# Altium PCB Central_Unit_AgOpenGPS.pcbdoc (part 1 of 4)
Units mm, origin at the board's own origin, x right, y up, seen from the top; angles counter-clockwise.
Board outline 200.19 x 122.57 mm, 2 copper layers (Top Layer, Bottom Layer); 271 components, 213 nets, 1023 pads, 412 vias.
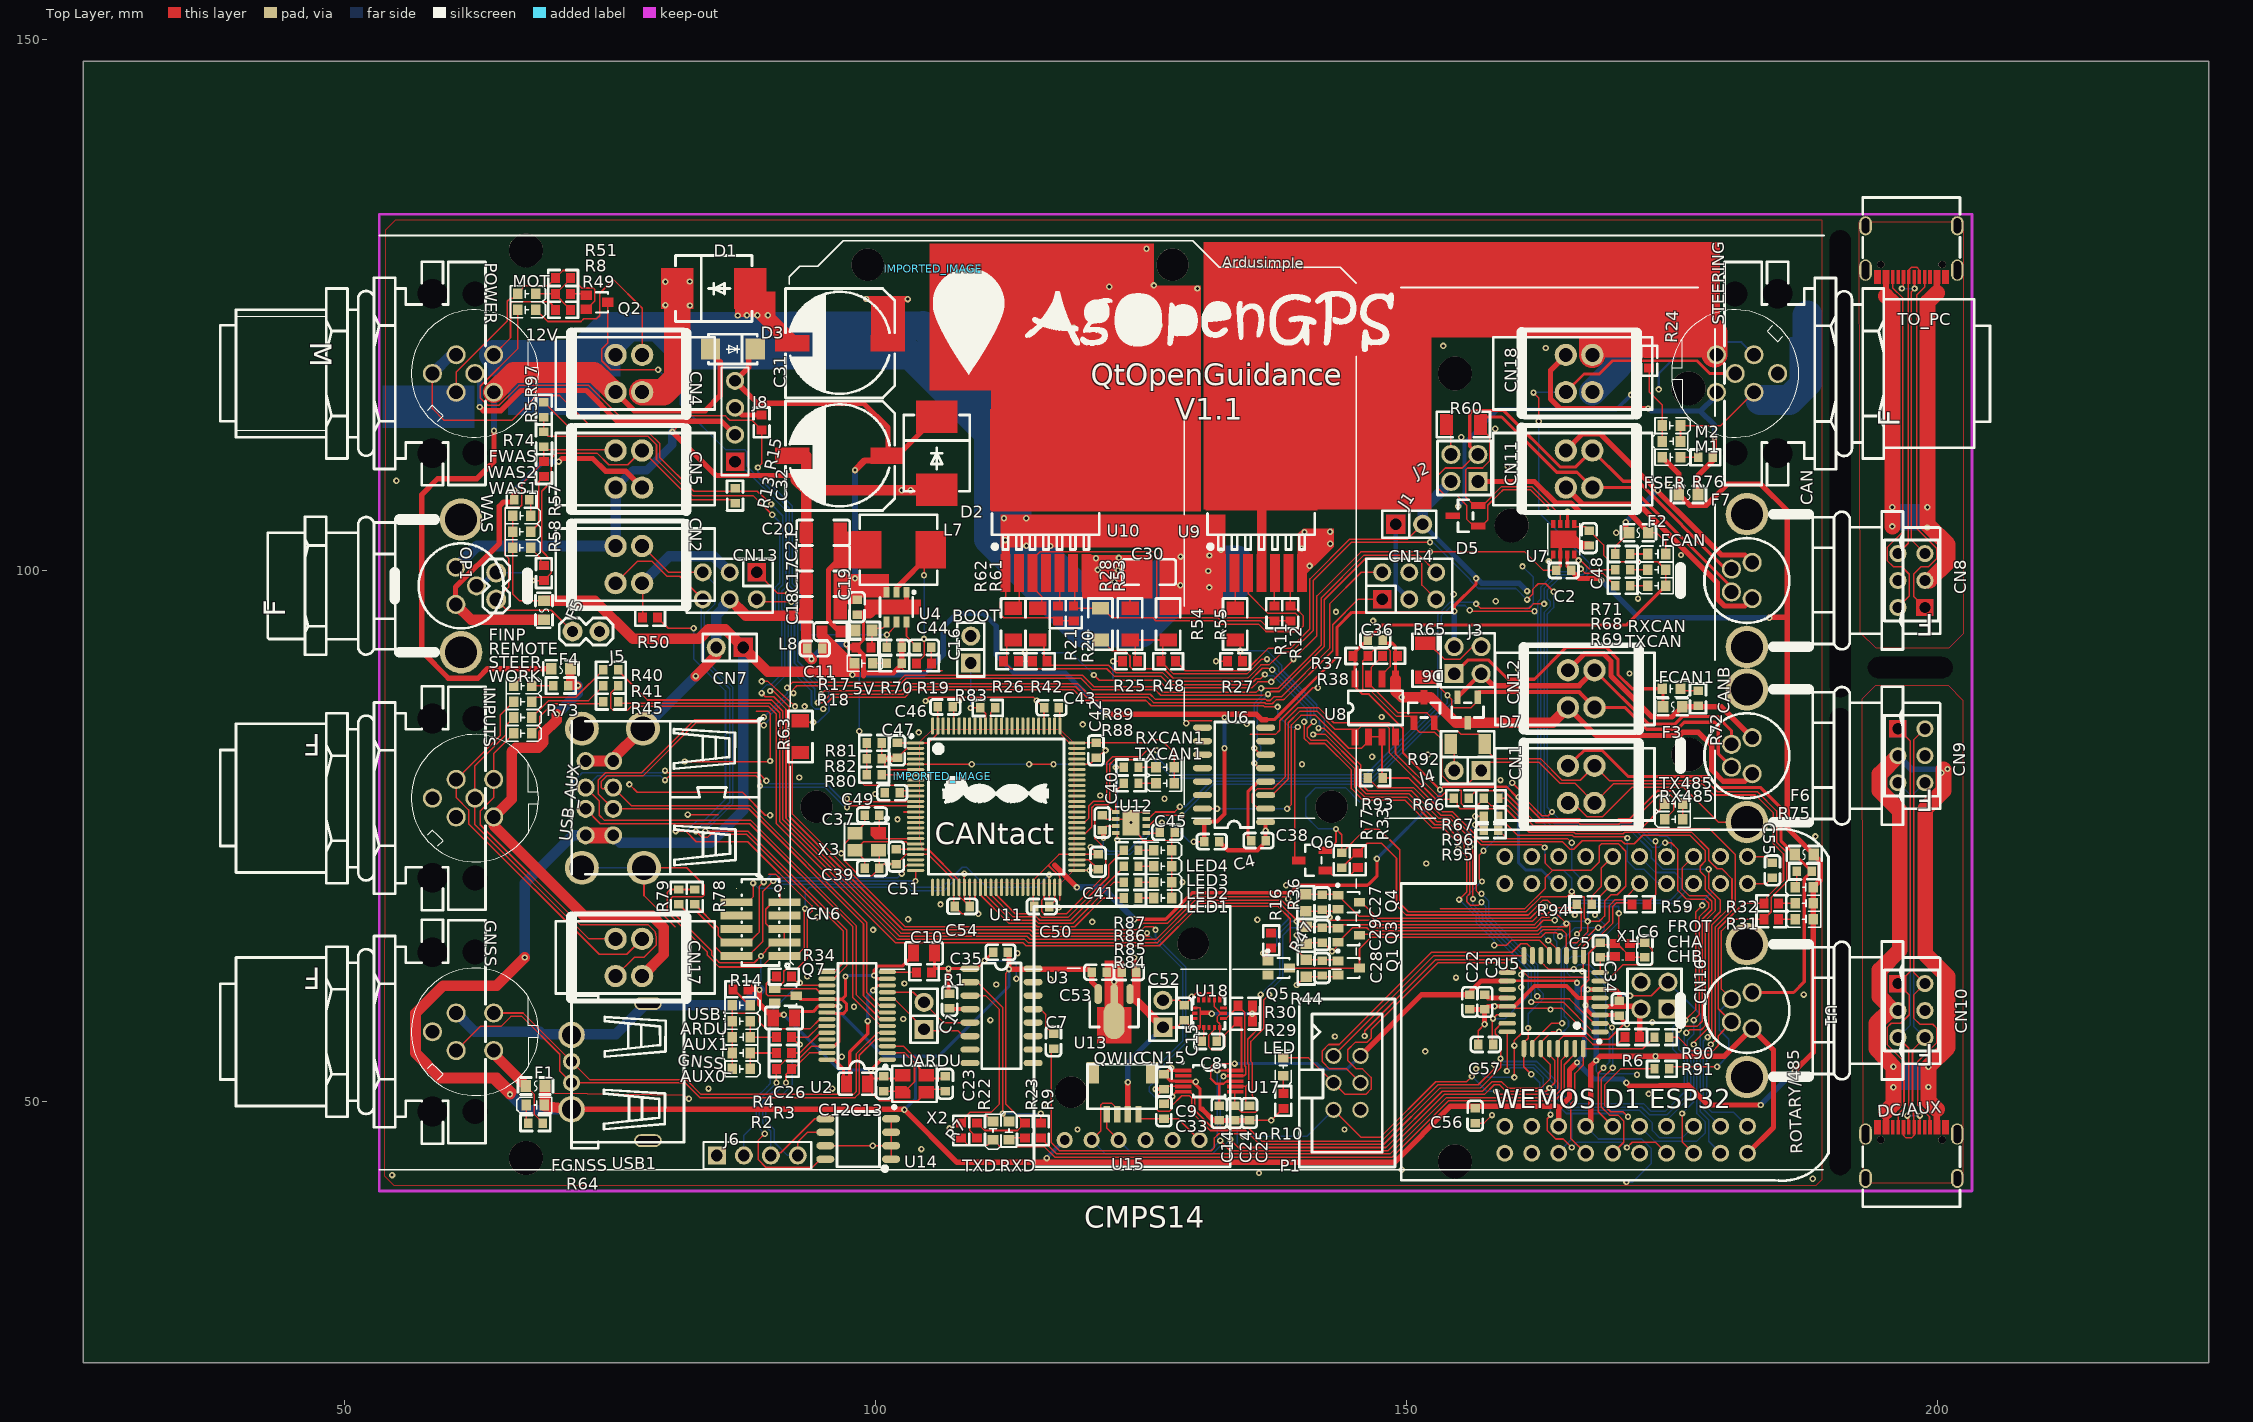
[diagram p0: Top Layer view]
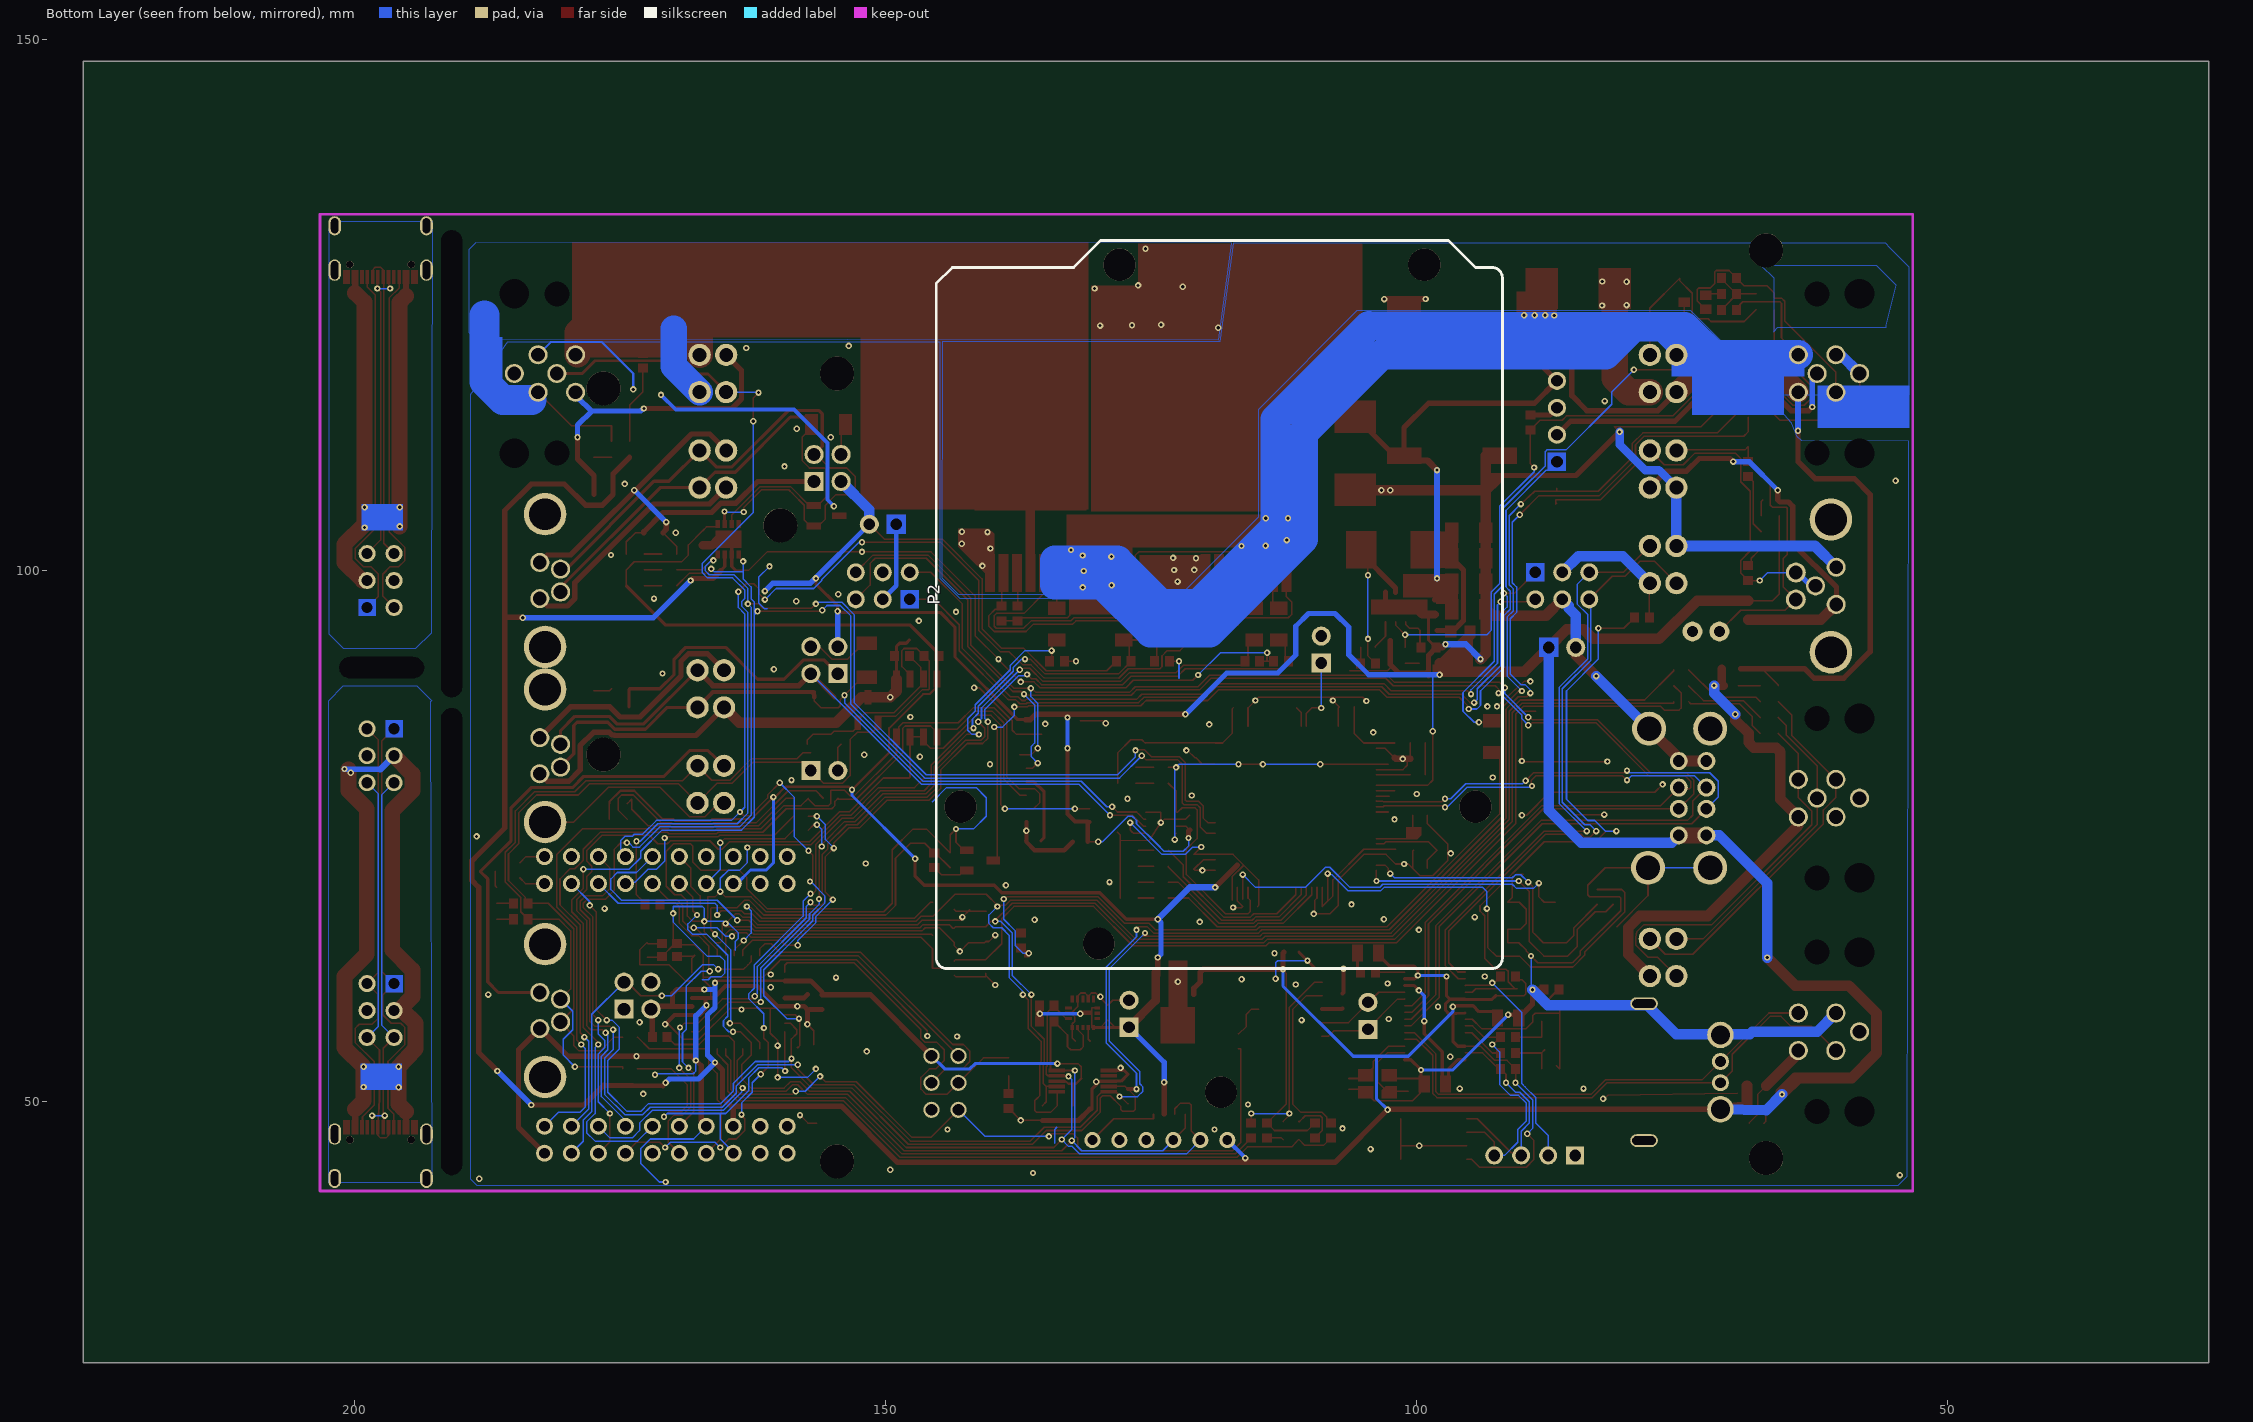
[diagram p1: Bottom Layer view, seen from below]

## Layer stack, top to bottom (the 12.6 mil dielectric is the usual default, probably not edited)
Top Layer: signal copper (thickness not stored)
Dielectric: dielectric 0.32, FR-4, Dk 4.8
Bottom Layer: signal copper (thickness not stored)

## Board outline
225.587,25.4 25.4,25.4 25.4,147.973 225.587,147.973

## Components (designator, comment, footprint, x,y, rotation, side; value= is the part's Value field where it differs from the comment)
5V "FC-D1608WD-460H5" LED0603-RD 98.887,91.266 r180 top
12V "FC-D1608WD-460H5" LED0603-RD 67.187,124.566 r180 top
ARDU "FC-D1608UGK-520D10" LED0603-RD 87.387,57.566 r180 top
AUX0 "FC-D1608UGK-520D10" LED0603-RD 87.387,53.066 r180 top
AUX1 "FC-DA1608BK-470H10" LED0603-RD 87.387,56.066 r0 top
BOOT "A2541WV-2P" HDR-TH_P2.54-H-M_A2541WV-2P#1 108.987,92.566 r90 top
C1 "1uF" C0603 106.987,59.466 r270 top
C2 "1uF" C0603 164.837,100.016 r180 top
C3 "100nF" C0603 157.387,59.366 r270 top
C4 "100nF" C0603 131.687,74.466 r0 top
C5 "22pF" C0603 168.287,64.266 r270 top
C6 "22pF" C0603 172.487,64.266 r90 top
C7 "100nF" C0603 116.787,55.666 r90 top
C8 "100nF" C0603 131.437,55.666 r180 top
C9 "100nF" C0603 127.187,51.866 r270 top
C10 "10uF" C0805 104.587,63.966 r180 top
C11 "1uF" C0603 94.287,92.666 r180 top
C12 "10uF" C0805 98.287,51.666 r180 top
C13 "33pF" C0603 100.787,51.666 r270 top
C14 "1uF" C0603 132.387,48.916 r270 top
C15 "1uF" C0603 129.087,58.366 r90 top
C16 "100nF" C0603 104.587,92.766 r0 top
C17 "10uF" C1206 95.087,98.766 r0 top
C18 "10uF" C1206 95.087,96.366 r0 top
C19 "100nF" C0603 98.287,96.566 r90 top
C20 "22uF" C1206 95.087,103.566 r0 top
C21 "22uF" C1206 95.087,101.166 r0 top
C22 "1uF" C0603 155.987,59.366 r270 top
C23 "33pF" C0603 106.587,51.666 r270 top
C24 "1nF" C0603 133.839,48.917 r90 top
C25 "1nF" C0603 135.239,48.917 r90 top
C26 "10uF" C0805 91.387,57.866 r180 top
C27 "100nF" C0603 142.087,68.766 r90 top
C28 "100nF" C0603 142.087,62.566 r90 top
C29 "100nF" C0603 142.087,65.666 r90 top
C30 "10uF" C1206 125.787,99.866 r180 top
C31 "470uF" CAP-SMD_BD10.0-L10.3-W10.3-FD 96.687,121.416 r180 top
C32 "470uF" CAP-SMD_BD10.0-L10.3-W10.3-FD 96.687,110.816 r180 top
C33 "100nF" C0603 127.187,49.066 r90 top
C34 "1uF" C0603 170.087,58.766 r270 top
C35 "1uF" C0603 111.787,64.066 r180 top
C36 "1uF" C0603 147.087,93.466 r0 top
C37 "33pF" C0603 99.687,76.966 r0 top
C38 "100nF" C0603 136.087,74.566 r0 top
C39 "33pF" C0603 99.687,71.966 r180 top
C40 "1uF" C0603 121.387,76.266 r90 top
C41 "1uF" C0603 120.987,72.566 r90 top
C42 "1uF" C0603 120.787,83.066 r90 top
C43 "1uF" C0603 116.587,87.066 r0 top
C44 "100nF" C0603 101.787,92.766 r180 top
C45 "100nF" C0603 127.487,75.366 r180 top
C46 "1uF" C0603 106.587,87.166 r180 top
C47 "1uF" C0603 102.087,83.066 r90 top
C48 "100nF" C0603 167.237,103.066 r90 top
C49 "1uF" C0603 101.587,79.066 r0 top
C50 "1uF" C0603 115.687,68.366 r180 top
C51 "1uF" C0603 101.987,73.066 r90 top
C52 "1uF" C0603 123.887,62.166 r180 top
C53 "1uF" C0603 121.087,62.166 r0 top
C54 "1uF" C0603 108.187,68.366 r0 top
C55 "100nF" C0603 184.487,71.766 r270 top
C56 "1uF" C0603 156.487,48.666 r270 top
C57 "1nF" C0603 157.487,55.366 r0 top
CAN "M8 4pole female" "M8 FEMALE 4POLE 90°" 182.087,99.066 r90 top
CANB "M8 4pole female" "M8 FEMALE 4POLE 90°" 182.087,82.566 r90 top
CHA "FC-D1608HYK-588J" LED0603-RD 187.487,68.666 r0 top
CHB "FC-D1608HOK-600H" LED0603-RD 187.487,67.166 r0 top
CN1 "4x1 push_in connector" "S2C-SMT 3.50/04/180G 3.5SN BK RL" 166.487,79.866 r270 top
CN2 "4x1 push_in connector" "S2C-SMT 3.50/04/180G 3.5SN BK RL" 76.787,100.566 r90 top
CN4 "4x1 push_in connector" "S2C-SMT 3.50/04/180G 3.5SN BK RL" 76.787,118.566 r90 top
CN5 "4x1 push_in connector" "S2C-SMT 3.50/04/180G 3.5SN BK RL" 76.787,109.566 r90 top
CN6 "1315-1206G0M075CP01" HDR-SMD_12P-P1.27-V-M-R2-C6-S7.50 89.187,66.866 r90 top
CN7 "A2541WV-2P" HDR-TH_P2.54-H-M_A2541WV-2P#2 86.287,92.766 r180 top
CN8 "A2541WV-2X3P" HDR-TH_6P-P2.54-V-R2-C3-S2.54_A2541WV-2X3P 197.587,99.066 r90 top
CN9 "A2541WV-2X3P" HDR-TH_6P-P2.54-V-R2-C3-S2.54_A2541WV-2X3P 197.587,82.566 r270 top
CN10 "A2541WV-2X3P" HDR-TH_6P-P2.54-V-R2-C3-S2.54_A2541WV-2X3P 197.587,58.566 r270 top
CN11 "4x1 push_in connector" "S2C-SMT 3.50/04/180G 3.5SN BK RL" 166.287,109.566 r270 top
CN12 "4x1 push_in connector" "S2C-SMT 3.50/04/180G 3.5SN BK RL" 166.487,88.866 r270 top
CN13 "PM254V-12-06-H85" HDR-TH_6P-P2.54-V-F-R2-C3-S2.54 86.287,98.566 r180 top
CN14 "PM254V-12-06-H85" HDR-TH_6P-P2.54-V-F-R2-C3-S2.54 150.287,98.566 r0 top
CN15 "A2541WV-2P" HDR-TH_P2.54-H-M_A2541WV-2P#1 127.087,58.266 r90 top
CN16 "A2541WV-2X2P" HDR-TH_4P-P2.54-V-R2-C2-S2.54_A2541WV-2X2P 173.387,59.966 r90 top
CN17 "4x1 push_in connector" "S2C-SMT 3.50/04/180G 3.5SN BK RL" 76.787,63.566 r90 top
CN18 "4x1 push_in connector" "S2C-SMT 3.50/04/180G 3.5SN BK RL" 166.287,118.566 r270 top
D1 "SMCJ28A-C140808" SMC_L6.9-W5.9-LS7.9-RD 84.787,126.566 r0 top
D2 "SMCJ28A-C140808" SMC_L6.9-W5.9-LS7.9-RD 105.787,111.066 r270 top
D3 "SS34_C83961" SMA_L4.4-W2.8-LS5.4-RD 86.587,120.866 r180 top
D5 "CDSOT23-T24CAN" SOT-23_L2.9-W1.3-P0.95-LS2.4-BR#1 155.587,105.166 r0 top
D6 "CDSOT23-T24CAN" SOT-23_L2.9-W1.3-P0.95-LS2.4-BR#1 151.687,86.866 r270 top
D7 "CDSOT23-T24CAN" SOT-23_L2.9-W1.3-P0.95-LS2.4-BR#2 155.787,86.866 r90 top
DC/AUX "KH-TYPE-C-16P" USB-C-SMD_KH-TYPE-C-16P#1 197.587,45.166 r0 top
F1 "BSMD0603-050-6V" F0603 67.987,51.466 r0 top
F2 "BSMD0603-050-6V" F0603 171.887,103.566 r180 top
F3 "BSMD0603-050-6V" F0603 175.087,87.166 r0 top
F4 "BSMD0603-050-6V" F0603 70.387,90.766 r0 top
F5 "BSMD0603-050-6V" F0603 68.787,96.266 r270 top
F6 "BSMD0603-050-6V" F0603 187.487,73.266 r180 top
F7 "BSMD0603-050-6V" F0603 176.587,107.166 r0 top
FCAN "FC-DA1608HRK-620D" LED0603-FD 173.587,101.566 r180 top
FCAN1 "FC-DA1608HRK-620D" LED0603-FD 174.988,88.867 r0 top
FGNSS "FC-DA1608HRK-620D" LED0603-FD 67.987,49.666 r180 top
FINP "FC-DA1608HRK-620D" LED0603-FD 66.787,89.166 r0 top
FROT "FC-DA1608HRK-620D" LED0603-FD 187.487,70.166 r180 top
FSER "FC-DA1608HRK-620D" LED0603-FD 174.987,110.666 r0 top
FWAS "FC-DA1608HRK-620D" LED0603-FD 66.687,105.166 r0 top
GNSS "M12 4pole female" "M12-D FEMALE 4POLE 90°" 62.287,56.566 r90 top
GNSS_ "FC-DA1608BK-470H10" LED0603-RD 87.387,54.566 r0 top
IMPORTED_IMAGE "IMPORTED_IMAGE" IMPORTED_IMAGE 106.327,80.618 r0 top
IMPORTED_IMAGE "IMPORTED_IMAGE" IMPORTED_IMAGE 105.442,128.45 r0 top
INPUTS "M12A 5pole female" "M12-A FEMALE 4-5POLE 90°" 62.287,78.566 r90 top
J1 "A2541WV-2P" HDR-TH_P2.54-H-M_A2541WV-2P#2 150.287,104.366 r0 top
J2 "A2541WV-2X2P" HDR-TH_4P-P2.54-V-R2-C2-S2.54_A2541WV-2X2P 155.487,109.666 r90 top
J3 "A2541WV-2X2P" HDR-TH_4P-P2.54-V-R2-C2-S2.54_A2541WV-2X2P 155.787,91.566 r0 top
J4 "A2541WV-2P" HDR-TH_P2.54-H-M_A2541WV-2P#1 155.787,81.166 r180 top
J5 "Option single ended WAS" 1X02#1 71.487,94.266 r0 top
J6 "A2541WV-4P" HDR-TH_4P-P2.54-V#1 88.887,44.916 r0 top
J8 "A2541WV-4P" HDR-TH_4P-P2.54-V#2 86.787,114.066 r90 top
L7 "5.6uH" IND-SMD_L7.3-W6.6_MHCI06030 102.187,101.966 r180 top
L8 "1500Ω" L0603 95.887,94.266 r180 top
LED "FC-DA1608HRK-620D" LED0603-FD 138.43,53.259 r270 top
LED1 "FC-D1608UGK-520D10" LED0603-RD 127.087,69.166 r180 top
LED2 "FC-DA1608BK-470H10" LED0603-RD 127.087,70.666 r180 top
LED3 "FC-D1608UGK-520D10" LED0603-RD 127.087,72.166 r180 top
LED4 "FC-DA1608BK-470H10" LED0603-RD 127.087,73.666 r180 top
M1 "FC-D1608HYK-588J" LED0603-RD 174.987,112.166 r0 top
M2 "FC-D1608HOK-600H" LED0603-RD 174.987,113.666 r180 top
MOT "FC-D1608WD-460H5" LED0603-RD 67.187,126.066 r180 top
OP1 "Option M8 4pole" 1X02#2 64.287,99.816 r270 top
P1 "HDR-IDC-2.54-2X3P" IDC-TH_6P-P2.54_C11214 144.429,51.758 r270 top
P2 "Ardusimple RTK2B Board" ARDUSIMPLE_MECH 118.587,103.666 r270 bottom
POWER "M12A 5pole male" "M12-A MALE 4-5POLE 90°" 62.287,118.566 r90 top
Q1 "2N7002WT1G" SOT-323-3_L2.0-W1.3-P1.30-LS2.1-BR 144.587,62.566 r180 top
Q2 "BC856BW,115" SOT-323-3_L2.2-W1.3-P1.30-LS2.2-BR#1 73.787,125.266 r180 top
Q3 "2N7002WT1G" SOT-323-3_L2.0-W1.3-P1.30-LS2.1-BR 144.587,65.666 r180 top
Q4 "2N7002WT1G" SOT-323-3_L2.0-W1.3-P1.30-LS2.1-BR 144.587,68.766 r180 top
Q5 "2N7002WT1G" SOT-323-3_L2.0-W1.3-P1.30-LS2.1-BR 137.987,62.566 r180 top
Q6 "ZXMS6004FFTA" SOT-23-3_L2.9-W1.6-P1.90-LS2.8-BR 141.137,72.716 r0 top
Q7 "BC856BW,115" SOT-323-3_L2.2-W1.3-P1.30-LS2.2-BR#2 91.537,59.966 r180 top
QWIIC "QWIIC SMD JST" "QWIIC CONNECTOR" 123.587,49.616 r180 top
R1 "2.7k" R0603#1 104.587,62.166 r180 top
R2 "10K" R0603#1 91.387,53.066 r180 top
R3 "1K" R0603#1 91.387,54.566 r180 top
R4 "1K" R0603#1 91.387,56.066 r0 top
R5 "2k2" R0603#2 68.787,112.366 r270 top
R6 "1K" R0603#1 171.287,56.066 r0 top
R7 "1K" R0603#1 108.087,47.266 r270 top
R8 "10K" R0603#1 70.587,126.066 r0 top
R9 "1K" R0603#1 115.587,47.266 r90 top
R10 "1K" R0603#1 138.429,50.058 r90 top
R11 "1K" R0603#1 137.587,95.966 r90 top
R12 "1K" R0603#1 139.087,95.966 r90 top
R13 "2k2" R0603#2 86.787,107.066 r270 top
R14 "1K" R0603#1 87.287,60.566 r180 top
R15 "10K" R0603#1 89.287,113.966 r90 top
R16 "10K" R0603#1 137.287,65.166 r90 top
R17 "51K" R0603#3 98.887,94.366 r180 top
R18 "10K" R0603#1 98.887,92.766 r0 top
R19 "10" R0603#1 104.587,91.266 r0 top
R20 "1K" R0603#1 118.687,95.966 r270 top
R21 "1K" R0603#1 117.187,95.966 r270 top
R22 "1K" R0603#1 109.587,47.266 r90 top
R23 "1K" R0603#1 114.087,47.266 r90 top
R24 "2.7k" R0603#1 172.887,119.766 r90 top
R25 "2k2" R0603#1 123.987,91.466 r180 top
R26 "2k2" R0603#1 112.787,91.466 r0 top
R27 "2k2" R0603#1 133.887,91.466 r180 top
R28 "8.2K" RES-SMD_L3.5-W1.5#1 121.187,94.966 r90 top
R29 "1K" R0603#1 134.839,57.517 r0 top
R30 "1K" R0603#1 134.839,59.017 r0 top
R31 "1K" R0603#1 184.387,67.166 r0 top
R32 "1K" R0603#1 184.387,68.666 r0 top
R33 "10K" R0603#1 145.437,72.716 r90 top
R34 "10K" R0603#1 91.387,61.766 r180 top
R36 "560" R0603#3 140.53,68.715 r90 top
R37 "1K" R0603#1 145.687,91.966 r180 top
R38 "1K" R0603#1 148.487,91.966 r0 top
R40 "2k2" R0603#2 75.087,90.666 r0 top
R41 "2k2" R0603#2 75.087,89.166 r0 top
R42 "2k2" R0603#1 115.487,91.466 r180 top
R44 "560" R0603#3 140.587,62.566 r90 top
R45 "2k2" R0603#2 75.087,87.666 r0 top
R47 "560" R0603#3 140.587,65.666 r90 top
R48 "10K" R0603#1 127.587,91.466 r180 top
R49 "10K" R0603#1 70.587,124.566 r0 top
R50 "10K" R0603#1 78.787,95.566 r0 top
R51 "10K" R0603#1 70.587,127.566 r180 top
R53 "8.2K" RES-SMD_L3.5-W1.5#2 123.987,94.966 r90 top
R54 "8.2K" RES-SMD_L3.5-W1.5#2 127.587,94.966 r90 top
R55 "8.2K" RES-SMD_L3.5-W1.5#2 133.887,94.966 r90 top
R57 "1K" R0603#1 68.787,109.566 r270 top
R58 "1K" R0603#1 68.787,99.766 r90 top
R59 "1K" R0603#1 171.987,68.566 r0 top
R60 "120" R1206#1 155.387,113.766 r180 top
R61 "8.2K" RES-SMD_L3.5-W1.5#2 115.287,94.966 r90 top
R62 "8.2K" RES-SMD_L3.5-W1.5#2 112.987,94.966 r270 top
R63 "8.2K" RES-SMD_L3.5-W1.5#2 92.937,84.366 r270 top
R64 "1K" R0603#2 67.987,47.966 r0 top
R65 "120" R1206#1 151.787,91.566 r90 top
R66 "1K" R0603#2 155.187,78.566 r180 top
R67 "1K" R0603#2 157.987,78.566 r180 top
R68 "1K" R0603#2 170.387,100.066 r180 top
R69 "1K" R0603#2 170.387,98.566 r180 top
R70 "10K" R0603#2 101.787,91.266 r180 top
R71 "2.7k" R0603#2 170.387,101.566 r180 top
R72 "2.7k" R0603#2 177.487,87.966 r270 top
R73 "10K" R0603#2 70.387,89.166 r0 top
R74 "10K" R0603#2 66.687,106.666 r180 top
R75 "1K" R0603#2 187.487,71.666 r0 top
R76 "1K" R0603#2 178.187,110.666 r180 top
R77 "10K" R0603#2 143.937,72.716 r90 top
R78 "10K" R0603#2 82.987,69.266 r270 top
R79 "10K" R0603#2 81.487,69.266 r270 top
R80 "10K" R0603#2 99.887,80.766 r180 top
R81 "2.7k" R0603#2 99.887,83.766 r0 top
R82 "10K" R0603#2 99.887,82.266 r0 top
R83 "10" R0603#2 110.587,87.066 r0 top
R84 "1K" R0603#2 124.087,69.166 r180 top
R85 "1K" R0603#2 124.087,70.666 r180 top
R86 "1K" R0603#2 124.087,72.166 r180 top
R87 "1K" R0603#2 124.087,73.666 r180 top
R88 "1K" R0603#2 124.087,79.966 r180 top
R89 "1K" R0603#2 124.087,81.466 r180 top
R90 "1K" R0603#2 174.087,56.066 r180 top
R91 "1K" R0603#2 174.087,53.066 r180 top
R92 "120" R1206#2 155.787,83.666 r0 top
R93 "10K" R0603#2 147.087,80.466 r180 top
R94 "1K" R0603#2 166.787,68.566 r180 top
R95 "1K" R0603#2 157.987,75.566 r180 top
R96 "1K" R0603#2 157.987,76.866 r180 top
R97 "10" R0603#2 68.787,115.166 r90 top
REMOTE "FC-D1608HYK-588J" LED0603-RD 66.787,87.666 r180 top
ROTARY/485 "M8 4pole female" "M8 FEMALE 4POLE 90°" 182.087,58.566 r90 top
RX485 "FC-D1608UGK-520D10" LED0603-RD 175.187,76.566 r0 top
RXCAN "FC-D1608UGK-520D10" LED0603-RD 173.587,100.066 r0 top
RXCAN1 "FC-D1608UGK-520D10" LED0603-RD 127.287,81.466 r0 top
RXD "FC-D1608UGK-520D10" LED0603-RD 112.587,47.266 r270 top
STEER "FC-D1608HYK-588J" LED0603-RD 66.787,86.166 r180 top
STEERING "M12A 5pole female" "M12-A FEMALE 4-5POLE 90°" 180.987,118.566 r270 top
TO_PC "KH-TYPE-C-16P" USB-C-SMD_KH-TYPE-C-16P#2 197.587,130.066 r180 top
TX485 "FC-DA1608BK-470H10" LED0603-RD 175.187,78.066 r0 top
TXCAN "FC-DA1608BK-470H10" LED0603-RD 173.587,98.566 r0 top
TXCAN1 "FC-DA1608BK-470H10" LED0603-RD 127.287,79.966 r0 top
TXD "FC-DA1608BK-470H10" LED0603-RD 111.087,47.266 r90 top
U1 "TG_WEMOS_D1_ESP32(CLONE)" "WEMOS-D1 ESP32" 184.687,73.066 r270 top
U2 "FE1.1S" SSOP-28_L9.9-W3.9-P0.64-LS6.0-BL 98.287,58.066 r90 top
U3 "CH340B" SOIC-16_L9.9-W3.9-P1.27-LS6.0-BL 111.887,58.066 r270 top
U4 "TPS56339" SOT-23-6_L2.9-W1.6-P0.95-LS2.8-BL 101.987,96.566 r180 top
U5 "ATMEGA328P-AU" TQFP-32_L7.0-W7.0-P0.80-LS9.0-BL 163.887,59.366 r90 top
U6 "CH340B" SOIC-16_L9.9-W3.9-P1.27-LS6.0-BL 133.787,80.766 r90 top
U7 "TJA1051TK/3,118" HVSON-8_L3.0-W3.0-P0.65-BL-EP#1 164.837,102.966 r0 top
U8 "KY3485LEEN" SO-8_L4.9-W3.9-P1.27-LS5.9-BL 147.087,87.066 r0 top
U9 "BTN8982TAAUMA1" TO-263-7_L10.2-W10.4-P1.27-LS14.4-B 136.387,105.116 r270 top
U10 "BTN8982TAAUMA1" TO-263-7_L10.2-W10.4-P1.27-LS14.4-B 116.087,105.116 r270 top
U11 "LPC54616J512BD100" TQFP-100_14X14X05P 105.387,85.366 r0 top
U12 "TJA1051TK/3,118" HVSON-8_L3.0-W3.0-P0.65-BL-EP#2 124.087,76.266 r270 top
U13 "UR133AG-33-AB3-B-R" SOT-89_L4.5-W2.5-P1.50-LS4.2-BR 122.487,58.866 r90 top
U14 "BL24C02F-PARC" SOP-8_L5.0-W4.0-P1.27-LS6.2-BL 98.387,46.466 r90 top
U15 "CMPS14" CMPS14 114.937,43.866 r90 top
U17 "ADS1115IDGSR" MSOP-10_L3.0-W3.0-P0.50-LS5.0-BL 131.439,51.917 r270 top
U18 "MMA8452QR1_C11360" QFN-16_L3.0-W3.0-P0.50-TL_MMA8452QR1 131.439,58.317 r90 top
UARDU "A2541WV-2P" HDR-TH_P2.54-H-M_A2541WV-2P#1 104.588,58.067 r90 top
USB1 "A/F90_C109354" USB-A-TH_USB-A-F-2 74.987,52.766 r90 top
USB: "FC-D1608UGK-520D10" LED0603-RD 87.387,59.066 r180 top
USB_AUX "Double layer DIP 90° white" USB-A-TH_USB-M-51 75.286,78.566 r90 top
WAS "M8 3pole female" "M8 FEMALE 3POLE 90°" 60.987,98.566 r270 top
WAS1 "FC-D1608HYK-588J" LED0603-RD 66.687,102.166 r180 top
WAS2 "FC-D1608HOK-600H" LED0603-RD 66.687,103.666 r180 top
WORK "FC-D1608HYK-588J" LED0603-RD 66.787,84.666 r180 top
X1 "16MHz" OSC-SMD_4P-L2.0-W1.6-BL 170.387,64.266 r0 top
X2 "12MHz" OSC-SMD_4P-L3.2-W2.5-BL#1 103.687,51.666 r0 top
X3 "12MHz" OSC-SMD_4P-L3.2-W2.5-BL#2 99.187,74.466 r180 top

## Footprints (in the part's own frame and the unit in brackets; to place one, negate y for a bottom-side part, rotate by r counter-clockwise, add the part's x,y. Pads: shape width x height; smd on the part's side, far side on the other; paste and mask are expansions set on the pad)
1X02#1 [mil]
  round 74 hole 40: 1(0,0) 2(100,0)
  silkscreen extent -50,-50 150,50
1X02#2 [mil]
  round 74 hole 51.18: 1(0,0) 2(100,0)
  silkscreen extent -50,-50 150,50
ARDUSIMPLE_MECH [mil]
  round 120 hole 120 unplated: ""(-990,-370) ""(-990,760) ""(1020,-960) ""(1020,950)
  silkscreen extent -1080,-1050 1620,1050
C0603 [mm]
  rect 0.8x0.9 smd: 1(-0.7,0) 2(0.7,0)
  silkscreen extent -1.4,-0.7 1.4,0.72
C0805 [mm]
  round 0 smd: 1(-1,0) 2(1,0)
  Top Layer region: -1.5,0.775 -0.5,0.775 -0.5,-0.775 -1.5,-0.775
  Top Layer region: 0.5,0.775 1.5,0.775 1.5,-0.775 0.5,-0.775
  silkscreen extent -1.75,-1.04 1.75,1.04
C1206 [mm]
  round 0 smd: 1(-1.6,0) 2(1.6,0)
  Top Layer region: -2.2,0.95 -1,0.95 -1,-0.95 -2.2,-0.95
  Top Layer region: 1,0.95 2.2,0.95 2.2,-0.95 1,-0.95
  silkscreen extent -2.5,-1.2 2.5,1.2
CAP-SMD_BD10.0-L10.3-W10.3-FD [mm]
  round 0 smd: 1(-4.5,0) 2(4.5,0)
  Top Layer region: -2.9,-0.75 -6.1,-0.75 -6.1,0.75 -2.9,0.75
  Top Layer region: 6.1,-0.75 2.9,-0.75 2.9,0.75 6.1,0.75
  silkscreen extent -5.15,-5.15 5.15,5.15
CMPS14 [mm]
  round 1.524 hole 0.914: 1(2.5,-2.9) 2(2.5,-5.44) 3(2.5,-7.98) 4(2.5,-10.52) 5(2.5,-13.06) 6(2.5,-15.6)
  round 3 hole 3 unplated: ""(7,-3.5) ""(21,-15)
  silkscreen extent 0,-18.5 24.5,0
F0603 [mm]
  rect 1x1.1 smd: 1(-0.9,0) 2(0.9,0)
  silkscreen extent -1.65,-0.8 1.65,0.8
HDR-SMD_12P-P1.27-V-M-R2-C6-S7.50 [mm]
  rect 0.74x3 smd: 1(-3.175,-2.25) 2(-3.175,2.25) 3(-1.905,-2.25) 4(-1.905,2.25) 5(-0.635,-2.25) 6(-0.635,2.25) 7(0.635,-2.25) 8(0.635,2.25) 9(1.905,-2.25) 10(1.905,2.25)
  rect 0.1x0.1 smd: 11(3.175,-2.25) 12(3.175,2.25)
  silkscreen extent -4.24,-2.72 4.06,1.78
HDR-TH_4P-P2.54-V#1 [mm]
  rect 1.7x1.7 hole 1.1: 1(-3.81,0)
  round 1.7 hole 1.1: 2(-1.27,0) 3(1.27,0) 4(3.81,0)
  silkscreen extent -5.08,-1.27 5.08,1.27
HDR-TH_4P-P2.54-V#2 [mm]
  round 0 hole 1.1: 1(-3.81,0)
  round 1.7 hole 1.1: 2(-1.27,0) 3(1.27,0) 4(3.81,0)
  Top Layer region: -4.66,0.85 -2.96,0.85 -2.96,-0.85 -4.66,-0.85
  Bottom Layer region: -4.66,0.85 -2.96,0.85 -2.96,-0.85 -4.66,-0.85
  silkscreen extent -5.08,-1.27 5.08,1.27
HDR-TH_4P-P2.54-V-R2-C2-S2.54_A2541WV-2X2P [mm]
  rect 1.8x1.8 hole 1.2: 1(-1.27,-1.27)
  round 1.8 hole 1.2: 2(-1.27,1.27) 3(1.27,-1.27) 4(1.27,1.27)
  silkscreen extent -2.54,-2.54 2.54,2.54
HDR-TH_6P-P2.54-V-F-R2-C3-S2.54 [mm]
  round 0 hole 1.1: 1(-2.54,-1.27)
  round 1.7 hole 1.1: 2(-2.54,1.27) 3(0,-1.27) 4(0,1.27) 5(2.54,-1.27) 6(2.54,1.27)
  Top Layer region: -3.39,-0.42 -1.69,-0.42 -1.69,-2.12 -3.39,-2.12
  Bottom Layer region: -3.39,-0.42 -1.69,-0.42 -1.69,-2.12 -3.39,-2.12
  silkscreen extent -4.04,-2.54 4.04,2.54
HDR-TH_6P-P2.54-V-R2-C3-S2.54_A2541WV-2X3P [mm]
  round 0 hole 1.05: 1(-2.54,-1.27)
  round 1.6 hole 1.05: 2(-2.54,1.27) 3(0,-1.27) 4(0,1.27) 5(2.54,-1.27) 6(2.54,1.27)
  Top Layer region: -3.34,-0.47 -1.74,-0.47 -1.74,-2.07 -3.34,-2.07
  Bottom Layer region: -3.34,-0.47 -1.74,-0.47 -1.74,-2.07 -3.34,-2.07
  silkscreen extent -3.81,-2.54 3.81,2.54
HDR-TH_P2.54-H-M_A2541WV-2P#1 [mm]
  rect 1.8x1.8 hole 1.1: 1(-1.27,0)
  round 1.8 hole 1.1: 2(1.27,0)
  silkscreen extent -2.54,-1.27 2.54,1.27
HDR-TH_P2.54-H-M_A2541WV-2P#2 [mm]
  round 0 hole 1.1: 1(-1.27,0)
  round 1.8 hole 1.1: 2(1.27,0)
  Top Layer region: -2.17,0.9 -0.37,0.9 -0.37,-0.9 -2.17,-0.9
  Bottom Layer region: -2.17,0.9 -0.37,0.9 -0.37,-0.9 -2.17,-0.9
  silkscreen extent -2.54,-1.27 2.54,1.27
HVSON-8_L3.0-W3.0-P0.65-BL-EP#1 [mil]
  round 0 smd: 1(-39,-56.4) 2(-13,-56.4) 3(13,-56.4) 4(39,-56.4) 5(39,56.4) 6(13,56.4) 7(-13,56.4) 8(-39,56.4) 9(0,0)
  Top Layer region: -46,-42.4 -32,-42.4 -32,-70.4 -46,-70.4
  Top Layer region: -20,-42.4 -6,-42.4 -6,-70.4 -20,-70.4
  Top Layer region: 6,-42.4 20,-42.4 20,-70.4 6,-70.4
  Top Layer region: 32,-42.4 46,-42.4 46,-70.4 32,-70.4
  Top Layer region: 32,70.4 46,70.4 46,42.4 32,42.4
  Top Layer region: 6,70.4 20,70.4 20,42.4 6,42.4
  Top Layer region: -20,70.4 -6,70.4 -6,42.4 -20,42.4
  Top Layer region: -46,70.4 -32,70.4 -32,42.4 -46,42.4
  Top Layer region: -47.24,31.5 47.24,31.5 47.24,-31.5 -47.24,-31.5
  silkscreen extent -59,-89 59,59
HVSON-8_L3.0-W3.0-P0.65-BL-EP#2 [mil]
  rect 14x28 smd: 1(-39,-56.4) 2(-13,-56.4) 3(13,-56.4) 4(39,-56.4) 5(39,56.4) 6(13,56.4) 7(-13,56.4) 8(-39,56.4)
  rect 94.49x62.99 smd: 9(0,0)
  silkscreen extent -59,-89 59,59
IDC-TH_6P-P2.54_C11214 [mil]
  round 60 hole 43.3: 1(-100,-50) 2(-100,50) 3(0,-50) 4(0,50) 5(100,-50) 6(100,50)
  silkscreen extent -311,-177 312,178
IMPORTED_IMAGE [mm]
  silkscreen extent 0,-2.57 10,0
IND-SMD_L7.3-W6.6_MHCI06030 [mm]
  round 0 smd: 1(-3.025,0) 2(3.025,0)
  Top Layer region: -4.425,1.75 -1.625,1.75 -1.625,-1.75 -4.425,-1.75
  Top Layer region: 1.625,1.75 4.425,1.75 4.425,-1.75 1.625,-1.75
  silkscreen extent -3.65,-3.3 3.65,3.3
L0603 [mm]
  round 0 smd: 1(-0.9,0) 2(0.9,0)
  Top Layer region: 0.4,0.55 1.4,0.55 1.4,-0.55 0.4,-0.55
  Top Layer region: -1.4,0.55 -0.4,0.55 -0.4,-0.55 -1.4,-0.55
  silkscreen extent -1.68,-0.85 1.68,0.85
LED0603-FD [mm]
  rect 0.9x1 smd: 1(-0.85,0) 2(0.85,0)
  silkscreen extent -1.55,-0.75 1.75,0.75
LED0603-RD [mm]
  rect 0.9x1 smd: 1(-0.85,0) 2(0.85,0)
  silkscreen extent -1.75,-0.75 1.55,0.75
"M8 FEMALE 3POLE 90°" [mm]
  round 1.8 hole 1.3: 1(1.75,-0.5) 3(-1.75,-0.5) 4(0,1.45)
  round 4 hole 3: Shield(-6.25,0) Shield(6.25,0)
  silkscreen extent -6.5,-18.2 6.5,6.25
"M8 FEMALE 4POLE 90°" [mm]
  round 1.8 hole 1.3: 1(1.7,-0.5) 2(1.075,1.45) 3(-1.7,-0.5) 4(-1.075,1.45)
  round 4 hole 3: Shield(-6.25,0) Shield(6.25,0)
  silkscreen extent -6.5,-18.2 6.5,6.25
"M12-A FEMALE 4-5POLE 90°" [mm]
  round 1.8 hole 1.3: 1(1.768,-1.768) 2(-1.768,-1.768) 3(-1.768,1.768) 4(1.768,1.768) 5(0,0) Shield(0,4)
  round 1 hole 2.35 unplated: ""(-7.5,0) ""(7.5,0)
  round 2.35 hole 2.8 unplated: ""(-7.5,4) ""(7.5,4)
  silkscreen extent -10.54,-6 10.54,24
"M12-A MALE 4-5POLE 90°" [mm]
  round 1.8 hole 1.3: 1(-1.768,-1.768) 2(1.768,-1.768) 3(1.768,1.768) 4(-1.768,1.768) 5(0,0) Shield(0,4)
  round 1 hole 2.35 unplated: ""(-7.5,0) ""(7.5,0)
  round 2.35 hole 2.8 unplated: ""(-7.5,4) ""(7.5,4)
  silkscreen extent -10.54,-6 10.54,24
"M12-D FEMALE 4POLE 90°" [mm]
  round 1.8 hole 1.3: 1(1.768,-1.768) 2(-1.768,-1.768) 3(-1.768,1.768) 4(1.768,1.768) Shield(0,4)
  round 1 hole 2.35 unplated: ""(-7.5,0) ""(7.5,0)
  round 2.35 hole 2.8 unplated: ""(-7.5,4) ""(7.5,4)
  silkscreen extent -10.54,-6 10.54,24
MSOP-10_L3.0-W3.0-P0.50-LS5.0-BL [mil]
  round 0 smd: 1(-39.37,-96.5) 2(-19.68,-96.5) 3(0,-96.5) 4(19.69,-96.5) 5(39.37,-96.5) 6(39.37,96.5) 7(19.69,96.5) 8(0,96.5) 9(-19.68,96.5) 10(-39.37,96.5)
  Top Layer region: -45.37,-126.03 -45.37,-66.97 -33.37,-66.97 -33.37,-126.03
  Top Layer region: -25.68,-126.03 -25.68,-66.97 -13.68,-66.97 -13.68,-126.03
  Top Layer region: -6,-126.03 -6,-66.97 6,-66.97 6,-126.03
  Top Layer region: 13.69,-126.03 13.69,-66.97 25.69,-66.97 25.69,-126.03
  Top Layer region: 33.37,-126.03 33.37,-66.97 45.37,-66.97 45.37,-126.03
  Top Layer region: 33.37,66.97 33.37,126.03 45.37,126.03 45.37,66.97
  Top Layer region: 13.69,66.97 13.69,126.03 25.69,126.03 25.69,66.97
  Top Layer region: -6,66.97 -6,126.03 6,126.03 6,66.97
  Top Layer region: -25.68,66.97 -25.68,126.03 -13.68,126.03 -13.68,66.97
  Top Layer region: -45.37,66.97 -45.37,126.03 -33.37,126.03 -33.37,66.97
  silkscreen extent -74,-103 59,59
OSC-SMD_4P-L2.0-W1.6-BL [mm]
  round 0 smd: 1(-0.7,-0.6) 2(0.7,-0.6) 3(0.7,0.6) 4(-0.7,0.6)
  Top Layer region: -1.15,1 -0.25,1 -0.25,0.2 -1.15,0.2
  Top Layer region: 0.25,1 1.15,1 1.15,0.2 0.25,0.2
  Top Layer region: 0.25,-0.2 1.15,-0.2 1.15,-1 0.25,-1
  Top Layer region: -1.15,-0.2 -0.25,-0.2 -0.25,-1 -1.15,-1
  silkscreen extent -1.3,-1.37 1.3,0.9
OSC-SMD_4P-L3.2-W2.5-BL#1 [mil]
  round 0 smd: 1(-43.31,-31.5) 2(43.31,-31.5) 3(43.31,31.5) 4(-43.31,31.5)
  Top Layer region: 15.75,54.14 70.86,54.14 70.86,8.87 15.75,8.87
  Top Layer region: -70.87,-8.86 -30,-8.86 -15.75,-23.78 -15.75,-54.13 -70.87,-54.13
  Top Layer region: -70.87,54.14 -15.75,54.14 -15.75,8.87 -70.87,8.87
  Top Layer region: 15.75,-8.86 70.86,-8.86 70.86,-54.13 15.75,-54.13
  silkscreen extent -83,-93 83,67
OSC-SMD_4P-L3.2-W2.5-BL#2 [mil]
  round 0 smd: 1(-43.31,-31.5)
  rect 55.12x45.28 smd: 2(43.31,-31.5) 3(43.31,31.5) 4(-43.31,31.5)
  Top Layer region: -70.87,-8.86 -30,-8.86 -15.75,-23.78 -15.76,-54.13 -70.87,-54.13
  silkscreen extent -83,-93 83,67
QFN-16_L3.0-W3.0-P0.50-TL_MMA8452QR1 [mm]
  round 0 smd: 1(-1.35,1) 2(-1.35,0.5) 3(-1.35,0) 4(-1.35,-0.5) 5(-1.35,-1) 6(-0.5,-1.35) 7(0,-1.35) 8(0.5,-1.35) 9(1.35,-1) 10(1.35,-0.5) 11(1.35,0) 12(1.35,0.5) 13(1.35,1) 14(0.5,1.35) 15(0,1.35) 16(-0.5,1.35)
  Top Layer region: -1.575,1.125 -1.125,1.125 -1.125,0.875 -1.575,0.875
  Top Layer region: -1.575,0.625 -1.125,0.625 -1.125,0.375 -1.575,0.375
  Top Layer region: -1.575,0.125 -1.125,0.125 -1.125,-0.125 -1.575,-0.125
  Top Layer region: -1.575,-0.375 -1.125,-0.375 -1.125,-0.625 -1.575,-0.625
  Top Layer region: -1.575,-0.875 -1.125,-0.875 -1.125,-1.125 -1.575,-1.125
  Top Layer region: -0.625,-1.65 -0.625,-1.05 -0.375,-1.05 -0.375,-1.65
  Top Layer region: -0.125,-1.65 -0.125,-1.05 0.125,-1.05 0.125,-1.65
  Top Layer region: 0.375,-1.65 0.375,-1.05 0.625,-1.05 0.625,-1.65
  Top Layer region: 1.65,-1.125 1.05,-1.125 1.05,-0.875 1.65,-0.875
  Top Layer region: 1.65,-0.625 1.05,-0.625 1.05,-0.375 1.65,-0.375
  Top Layer region: 1.65,-0.125 1.05,-0.125 1.05,0.125 1.65,0.125
  Top Layer region: 1.65,0.375 1.05,0.375 1.05,0.625 1.65,0.625
  Top Layer region: 1.65,0.875 1.05,0.875 1.05,1.125 1.65,1.125
  Top Layer region: 0.625,1.575 0.625,1.125 0.375,1.125 0.375,1.575
  Top Layer region: 0.125,1.575 0.125,1.125 -0.125,1.125 -0.125,1.575
  Top Layer region: -0.375,1.575 -0.375,1.125 -0.625,1.125 -0.625,1.575
  silkscreen extent -1.98,-1.5 1.5,1.5
"QWIIC CONNECTOR" [mm]
  rect 0.6x1.55 smd: 1(-1.2,0.8) 2(-0.2,0.8) 3(0.8,0.8) 4(1.8,0.8)
  rect 1.2x2 smd: 5(3.1,-3.1) 6(-2.5,-3.1)
  silkscreen extent -2.9,-3.9 3.6,0.3
R0603#1 [mm]
  round 0 smd: 1(-0.7,0) 2(0.7,0)
  Top Layer region: 0.3,0.45 1.1,0.45 1.1,-0.45 0.3,-0.45
  Top Layer region: -1.1,0.45 -0.3,0.45 -0.3,-0.45 -1.1,-0.45
  silkscreen extent -1.4,-0.75 1.4,0.76
R0603#2 [mm]
  rect 0.8x0.9 smd: 1(-0.7,0) 2(0.7,0)
  silkscreen extent -1.4,-0.75 1.4,0.76
R0603#3 [mm]
  rect 1x1.1 smd: 1(-0.8,0) 2(0.8,0)
  silkscreen extent -1.55,-0.8 1.55,0.81
R1206#1 [mm]
  round 0 smd: 1(-1.6,0) 2(1.6,0)
  Top Layer region: 1,0.95 2.2,0.95 2.2,-0.95 1,-0.95
  Top Layer region: -2.2,0.95 -1,0.95 -1,-0.95 -2.2,-0.95
  silkscreen extent -2.5,-1.2 2.5,1.2
R1206#2 [mm]
  rect 1.2x1.9 smd: 1(-1.6,0) 2(1.6,0)
  silkscreen extent -2.5,-1.2 2.5,1.2
RES-SMD_L3.5-W1.5#1 [mm]
  rect 1.2x1.6 smd: 1(-1.5,0) 2(1.5,0)
  silkscreen extent -2.41,-1.14 2.41,1.14
RES-SMD_L3.5-W1.5#2 [mm]
  round 0 smd: 1(-1.5,0) 2(1.5,0)
  Top Layer region: -2.1,0.8 -0.9,0.8 -0.9,-0.8 -2.1,-0.8
  Top Layer region: 0.9,0.8 2.1,0.8 2.1,-0.8 0.9,-0.8
  silkscreen extent -2.41,-1.14 2.41,1.14
"S2C-SMT 3.50/04/180G 3.5SN BK RL" [mm]
  round 2.1 hole 1.3: 1(-1.75,-1.25) 2(-1.75,1.25) 3(1.75,-1.25) 4(1.75,1.25)
  silkscreen extent -4.1,-8.1 4.1,6.9
SMA_L4.4-W2.8-LS5.4-RD [mm]
  rect 1.8x2 smd: 1(-2.1,0) 2(2.1,0)
  silkscreen extent -2.3,-1.4 2.3,1.4
SMC_L6.9-W5.9-LS7.9-RD [mm]
  round 0 smd: 1(-3.435,0) 2(3.435,0)
  Top Layer region: 4.95,-1.91 1.92,-1.91 1.92,1.91 4.95,1.91
  Top Layer region: -1.92,-1.91 -4.95,-1.91 -4.95,1.91 -1.92,1.91
  silkscreen extent -3.6,-3.11 3.6,3.11
SO-8_L4.9-W3.9-P1.27-LS5.9-BL [mm]
  round 0 smd: 1(-1.905,-2.72) 2(-0.635,-2.72) 3(0.635,-2.72) 4(1.905,-2.72) 5(1.905,2.72) 6(0.635,2.72) 7(-0.635,2.72) 8(-1.905,2.72)
  Top Layer region: -2.23,-1.945 -1.58,-1.945 -1.58,-3.495 -2.23,-3.495
  Top Layer region: -0.96,-1.945 -0.31,-1.945 -0.31,-3.495 -0.96,-3.495
  Top Layer region: 0.31,-1.945 0.96,-1.945 0.96,-3.495 0.31,-3.495
  Top Layer region: 1.58,-1.945 2.23,-1.945 2.23,-3.495 1.58,-3.495
  Top Layer region: 1.58,3.495 2.23,3.495 2.23,1.945 1.58,1.945
  Top Layer region: 0.31,3.495 0.96,3.495 0.96,1.945 0.31,1.945
  Top Layer region: -0.96,3.495 -0.31,3.495 -0.31,1.945 -0.96,1.945
  Top Layer region: -2.23,3.495 -1.58,3.495 -1.58,1.945 -2.23,1.945
  silkscreen extent -2.54,-1.61 2.6,1.63
SOIC-16_L9.9-W3.9-P1.27-LS6.0-BL [mm]
  oval 0.6x1.798 smd: 1(-4.445,-2.972) 2(-3.175,-2.972) 3(-1.905,-2.972) 4(-0.635,-2.972) 5(0.635,-2.972) 6(1.905,-2.972) 7(3.175,-2.972) 8(4.445,-2.972) 9(4.445,2.972) 10(3.175,2.972) 11(1.905,2.972) 12(0.635,2.972) 13(-0.635,2.972) 14(-1.905,2.972) 15(-3.175,2.972) 16(-4.445,2.972)
  silkscreen extent -4.98,-1.85 4.98,1.83
SOP-8_L5.0-W4.0-P1.27-LS6.2-BL [mm]
  oval 0.7x1.7 smd: 1(-1.905,-3.1) 2(-0.635,-3.1) 3(0.635,-3.1) 4(1.905,-3.1) 5(1.905,3.1) 6(0.635,3.1) 7(-0.635,3.1) 8(-1.905,3.1)
  silkscreen extent -2.99,-2.71 2.6,2
SOT-23-3_L2.9-W1.6-P1.90-LS2.8-BR [mm]
  round 0 smd: 1(1.25,-0.95) 2(1.25,0.95) 3(-1.25,0)
  Top Layer region: -0.625,0.35 -0.625,-0.35 -1.875,-0.35 -1.875,0.35
  Top Layer region: 1.875,1.3 1.875,0.6 0.625,0.6 0.625,1.3
  Top Layer region: 1.875,-0.6 1.875,-1.3 0.625,-1.3 0.625,-0.6
  silkscreen extent -0.65,-1.46 0.9,1.46
SOT-23-6_L2.9-W1.6-P0.95-LS2.8-BL [mm]
  rect 0.55x1 smd: 1(-0.95,-1.4) 2(0,-1.4) 3(0.95,-1.4) 4(0.95,1.4) 5(0,1.4) 6(-0.95,1.4)
  silkscreen extent -1.78,-1.52 1.55,0.9
SOT-23_L2.9-W1.3-P0.95-LS2.4-BR#1 [mm]
  round 0 smd: 1(1.2,-0.95) 2(1.2,0.95) 3(-1.2,0)
  Top Layer region: 1.85,0.65 0.55,0.65 0.55,1.25 1.85,1.25
  Top Layer region: -0.55,-0.3 -1.85,-0.3 -1.85,0.3 -0.55,0.3
  Top Layer region: 1.85,-1.25 0.55,-1.25 0.55,-0.65 1.85,-0.65
  silkscreen extent -0.7,-1.5 0.7,1.5
SOT-23_L2.9-W1.3-P0.95-LS2.4-BR#2 [mm]
  rect 1.3x0.6 smd: 1(1.2,-0.95) 2(1.2,0.95) 3(-1.2,0)
  silkscreen extent -0.7,-1.5 0.7,1.5
SOT-89_L4.5-W2.5-P1.50-LS4.2-BR [mm]
  oval 1.9x0.7 smd: 1(1.25,-1.5) 3(1.25,1.5)
  oval 3.5x2 smd: 2(-1.25,0)
  oval 2.1x0.7 smd: 2(1.151,0)
  silkscreen extent -1.85,-2.3 0.75,2.3
SOT-323-3_L2.0-W1.3-P1.30-LS2.1-BR [mil]
  rect 41.5x32.5 smd: 1(40,-26) 2(40,26) 3(-40,0)
  silkscreen extent -40,-68 45,37
SOT-323-3_L2.2-W1.3-P1.30-LS2.2-BR#1 [mil]
  round 0 smd: 1(40,-26) 2(40,26) 3(-40,0)
  Top Layer region: 19.25,-42.25 19.25,-9.75 60.75,-9.75 60.75,-42.25
  Top Layer region: 19.25,9.75 19.25,42.25 60.75,42.25 60.75,9.75
  Top Layer region: -60.75,-16.25 -60.75,16.25 -19.25,16.25 -19.25,-16.25
  silkscreen extent -40,-37 4,37
SOT-323-3_L2.2-W1.3-P1.30-LS2.2-BR#2 [mil]
  rect 41.5x32.5 smd: 1(40,-26) 2(40,26) 3(-40,0)
  silkscreen extent -40,-37 4,37
SSOP-28_L9.9-W3.9-P0.64-LS6.0-BL [mil]
  oval 15.75x64.06 smd: 1(-162.5,-112) 2(-137.5,-112) 3(-112.5,-112) 4(-87.5,-112) 5(-62.5,-112) 6(-37.5,-112) 7(-12.5,-112) 8(12.5,-112) 9(37.5,-112) 10(62.5,-112) 11(87.5,-112) 12(112.5,-112) 13(137.5,-112) 14(162.5,-112) 15(162.5,112) 16(137.5,112) 17(112.5,112) 18(87.5,112) 19(62.5,112) 20(37.5,112) 21(12.5,112) 22(-12.5,112) 23(-37.5,112) 24(-62.5,112) 25(-87.5,112) 26(-112.5,112) 27(-137.5,112) 28(-162.5,112)
  silkscreen extent -195,-111 195,71
TO-263-7_L10.2-W10.4-P1.27-LS14.4-B [mil]
  round 0 smd: 1(210,-150) 2(210,-100) 3(210,-50) 4(210,0) 5(210,50) 6(210,100) 7(210,150) 8(-210,0)
  Top Layer region: -22.99,206.69 -22.99,-206.69 -397.01,-206.69 -397.01,206.69
  Top Layer region: 278.9,167.72 278.9,132.28 141.1,132.28 141.1,167.72
  Top Layer region: 278.9,117.72 278.9,82.28 141.1,82.28 141.1,117.72
  Top Layer region: 278.9,67.72 278.9,32.28 141.1,32.28 141.1,67.72
  Top Layer region: 278.9,17.72 278.9,-17.72 141.1,-17.72 141.1,17.72
  Top Layer region: 278.9,-32.28 278.9,-67.72 141.1,-67.72 141.1,-32.28
  Top Layer region: 278.9,-82.28 278.9,-117.72 141.1,-117.72 141.1,-82.28
  Top Layer region: 278.9,-132.28 278.9,-167.72 141.1,-167.72 141.1,-132.28
  silkscreen extent -10,-201 123,197
TQFP-32_L7.0-W7.0-P0.80-LS9.0-BL [mm]
  oval 0.45x1.65 smd: 1(-2.817,-4.369) 2(-2.017,-4.369) 3(-1.217,-4.369) 4(-0.417,-4.369) 5(0.381,-4.369) 6(1.181,-4.369) 7(1.981,-4.369) 8(2.781,-4.369) 17(2.791,4.369) 18(1.991,4.369) 19(1.191,4.369) 20(0.391,4.369) 21(-0.406,4.369) 22(-1.207,4.369) 23(-2.007,4.369) 24(-2.807,4.369)
  oval 1.65x0.45 smd: 9(4.381,-2.804) 10(4.381,-2.004) 11(4.381,-1.204) 12(4.381,-0.404) 13(4.381,0.394) 14(4.381,1.194) 15(4.381,1.994) 16(4.381,2.794) 25(-4.381,2.804) 26(-4.381,2.004) 27(-4.381,1.204) 28(-4.381,0.404) 29(-4.381,-0.394) 30(-4.381,-1.194) 31(-4.381,-1.994) 32(-4.381,-2.794)
  silkscreen extent -3.86,-4.45 2.94,2.95
TQFP-100_14X14X05P [mm]
  oval 1.646x0.28 smd: 1(-1.6,-1.6) 2(-1.6,-2.1) 3(-1.6,-2.6) 4(-1.6,-3.1) 5(-1.6,-3.6) 6(-1.6,-4.1) 7(-1.6,-4.6) 8(-1.6,-5.1) 9(-1.6,-5.6) 10(-1.6,-6.1) 11(-1.6,-6.6) 12(-1.6,-7.1) 13(-1.6,-7.6) 14(-1.6,-8.1) 15(-1.6,-8.6) 16(-1.6,-9.1) 17(-1.6,-9.6) 18(-1.6,-10.1) 19(-1.6,-10.6) 20(-1.6,-11.1) 21(-1.6,-11.6) 22(-1.6,-12.1) 23(-1.6,-12.6) 24(-1.6,-13.1) 25(-1.6,-13.6) 51(13.6,-13.6) 52(13.6,-13.1) 53(13.6,-12.6) 54(13.6,-12.1) 55(13.6,-11.6) 56(13.6,-11.1) 57(13.6,-10.6) 58(13.6,-10.1) 59(13.6,-9.6) 60(13.6,-9.1) 61(13.6,-8.6) 62(13.6,-8.1) 63(13.6,-7.6) 64(13.6,-7.1) 65(13.6,-6.6) 66(13.6,-6.1) 67(13.6,-5.6) 68(13.6,-5.1) 69(13.6,-4.6) 70(13.6,-4.1) 71(13.6,-3.6) 72(13.6,-3.1) 73(13.6,-2.6) 74(13.6,-2.1) 75(13.6,-1.6)
  oval 0.28x1.646 smd: 26(0,-15.2) 27(0.5,-15.2) 28(1,-15.2) 29(1.5,-15.2) 30(2,-15.2) 31(2.5,-15.2) 32(3,-15.2) 33(3.5,-15.2) 34(4,-15.2) 35(4.5,-15.2) 36(5,-15.2) 37(5.5,-15.2) 38(6,-15.2) 39(6.5,-15.2) 40(7,-15.2) 41(7.5,-15.2) 42(8,-15.2) 43(8.5,-15.2) 44(9,-15.2) 45(9.5,-15.2) 46(10,-15.2) 47(10.5,-15.2) 48(11,-15.2) 49(11.5,-15.2) 50(12,-15.2) 76(12,0) 77(11.5,0) 78(11,0) 79(10.5,0) 80(10,0) 81(9.5,0) 82(9,0) 83(8.5,0) 84(8,0) 85(7.5,0) 86(7,0) 87(6.5,0) 88(6,0) 89(5.5,0) 90(5,0) 91(4.5,0) 92(4,0) 93(3.5,0) 94(3,0) 95(2.5,0) 96(2,0) 97(1.5,0) 98(1,0) 99(0.5,0) 100(0,0)
  silkscreen extent -2.15,-13.98 12.37,-0.8
USB-A-TH_USB-A-F-2 [mm]
  oval 1.2x2.6 hole 0.8 slot 2.2 at 90 deg: 0(-6.45,-3.6) 0(6.45,-3.6)
  round 2.5 hole 1.8: 1(-3.5,3.6) 4(3.5,3.6)
  round 1.6 hole 1: 2(-1,3.6) 3(1,3.6)
  silkscreen extent -7.16,-7 7.18,3.6
USB-A-TH_USB-M-51 [mm]
  round 1.7 hole 1.1: 1(-3.5,2.574) 2(-1.001,2.574) 3(1.001,2.574) 4(3.5,2.574) 5(-3.5,-0.027) 6(-1.001,-0.027) 7(1.001,-0.027) 8(3.5,-0.027)
  round 3.2 hole 2.3: 9(-6.551,-2.925) 9(-6.551,2.925) 9(6.551,-2.826) 9(6.551,2.925)
  silkscreen extent -7.52,-14.13 7.54,3.87
USB-C-SMD_KH-TYPE-C-16P#1 [mm]
  oval 1.2x2 hole 0.7 slot 1.7 at 90 deg copper offset 0,0: 1(-4.32,1.765) 2(4.32,1.765)
  oval 1.2x1.8 hole 0.7 slot 1.4 at 90 deg copper offset 0,0: 3(-4.32,-2.415)
  oval 1.2x1.8 hole 0.7 slot 1.4 at 90 deg: 4(4.32,-2.415)
  round 0 smd: A1(-3.35,2.415) A4(-2.55,2.415) A5(-1.25,2.415) A6(-0.25,2.415) A7(0.25,2.415) A8(1.25,2.415) A9(2.55,2.415) A12(3.35,2.415) B1(3.05,2.415) B4(2.25,2.415) B5(1.75,2.415) B6(0.75,2.415) B7(-0.75,2.415) B8(-1.75,2.415) B9(-2.25,2.415) B12(-3.05,2.415)
  round 0.7 hole 0.7 unplated: ""(-2.89,1.235) ""(2.89,1.235)
  Top Layer region: -3.5,3.065 -3.2,3.065 -3.2,1.765 -3.5,1.765
  Top Layer region: -3.2,3.065 -2.9,3.065 -2.9,1.765 -3.2,1.765
  Top Layer region: -2.7,3.065 -2.4,3.065 -2.4,1.765 -2.7,1.765
  Top Layer region: -2.4,3.065 -2.1,3.065 -2.1,1.765 -2.4,1.765
  Top Layer region: -1.9,3.065 -1.6,3.065 -1.6,1.765 -1.9,1.765
  Top Layer region: -1.4,3.065 -1.1,3.065 -1.1,1.765 -1.4,1.765
  Top Layer region: -0.9,3.065 -0.6,3.065 -0.6,1.765 -0.9,1.765
  Top Layer region: -0.4,3.065 -0.1,3.065 -0.1,1.765 -0.4,1.765
  Top Layer region: 0.1,3.065 0.4,3.065 0.4,1.765 0.1,1.765
  Top Layer region: 0.6,3.065 0.9,3.065 0.9,1.765 0.6,1.765
  Top Layer region: 1.1,3.065 1.4,3.065 1.4,1.765 1.1,1.765
  Top Layer region: 1.6,3.065 1.9,3.065 1.9,1.765 1.6,1.765
  Top Layer region: 2.1,3.065 2.4,3.065 2.4,1.765 2.1,1.765
  Top Layer region: 2.4,3.065 2.7,3.065 2.7,1.765 2.4,1.765
  Top Layer region: 2.9,3.065 3.2,3.065 3.2,1.765 2.9,1.765
  Top Layer region: 3.2,3.065 3.5,3.065 3.5,1.765 3.2,1.765
  silkscreen extent -4.57,-5.08 4.57,0.57
USB-C-SMD_KH-TYPE-C-16P#2 [mm]
  oval 1.2x2 hole 0.7 slot 1.7 at 90 deg copper offset 0,0: 1(-4.32,1.765) 2(4.32,1.765)
  oval 1.2x1.8 hole 0.7 slot 1.4 at 90 deg: 3(-4.32,-2.415)
  oval 1.2x1.8 hole 0.7 slot 1.4 at 90 deg copper offset 0,0: 4(4.32,-2.415)
  round 0 smd: A1(-3.35,2.415) A4(-2.55,2.415) A5(-1.25,2.415) A6(-0.25,2.415) A7(0.25,2.415) A8(1.25,2.415) A9(2.55,2.415) A12(3.35,2.415) B1(3.05,2.415) B4(2.25,2.415) B5(1.75,2.415) B6(0.75,2.415) B7(-0.75,2.415) B8(-1.75,2.415) B9(-2.25,2.415) B12(-3.05,2.415)
  round 0.7 hole 0.7 unplated: ""(-2.89,1.235) ""(2.89,1.235)
  Top Layer region: -3.5,3.065 -3.2,3.065 -3.2,1.765 -3.5,1.765
  Top Layer region: -3.2,3.065 -2.9,3.065 -2.9,1.765 -3.2,1.765
  Top Layer region: -2.7,3.065 -2.4,3.065 -2.4,1.765 -2.7,1.765
  Top Layer region: -2.4,3.065 -2.1,3.065 -2.1,1.765 -2.4,1.765
  Top Layer region: -1.9,3.065 -1.6,3.065 -1.6,1.765 -1.9,1.765
  Top Layer region: -1.4,3.065 -1.1,3.065 -1.1,1.765 -1.4,1.765
  Top Layer region: -0.9,3.065 -0.6,3.065 -0.6,1.765 -0.9,1.765
  Top Layer region: -0.4,3.065 -0.1,3.065 -0.1,1.765 -0.4,1.765
  Top Layer region: 0.1,3.065 0.4,3.065 0.4,1.765 0.1,1.765
  Top Layer region: 0.6,3.065 0.9,3.065 0.9,1.765 0.6,1.765
  Top Layer region: 1.1,3.065 1.4,3.065 1.4,1.765 1.1,1.765
  Top Layer region: 1.6,3.065 1.9,3.065 1.9,1.765 1.6,1.765
  Top Layer region: 2.1,3.065 2.4,3.065 2.4,1.765 2.1,1.765
  Top Layer region: 2.4,3.065 2.7,3.065 2.7,1.765 2.4,1.765
  Top Layer region: 2.9,3.065 3.2,3.065 3.2,1.765 2.9,1.765
  Top Layer region: 3.2,3.065 3.5,3.065 3.5,1.765 3.2,1.765
  silkscreen extent -4.57,-5.08 4.57,0.57
"WEMOS-D1 ESP32" [mm]
  round 1.6 hole 1.016: 1(0,-2.54) 2(2.54,-2.54) 3(25.4,-2.54) 4(27.94,-2.54) 5(0,-5.08) 6(2.54,-5.08) 7(25.4,-5.08) 8(27.94,-5.08) 9(0,-7.62) 10(2.54,-7.62) 11(25.4,-7.62) 12(27.94,-7.62) 13(0,-10.16) 14(2.54,-10.16) 15(25.4,-10.16) 16(27.94,-10.16) 17(0,-12.7) 18(2.54,-12.7) 19(25.4,-12.7) 20(27.94,-12.7) 21(0,-15.24) 22(2.54,-15.24) 23(25.4,-15.24) 24(27.94,-15.24) 25(0,-17.78) 26(2.54,-17.78) 27(25.4,-17.78) 28(27.94,-17.78) 29(0,-20.32) 30(2.54,-20.32) 31(25.4,-20.32) 32(27.94,-20.32) 33(0,-22.86) 34(2.54,-22.86) 35(25.4,-22.86) 36(27.94,-22.86) 37(0,-25.4) 38(25.4,-25.4) 39(2.54,-25.4) 40(27.94,-25.4)
  silkscreen extent -2.59,-35.16 30.53,5.08

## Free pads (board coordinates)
  round 0 hole 2 slot 44 at 90 deg unplated: 1(190.887,65.066) 1(190.887,110.066)
  round 0 hole 2 slot 8 at 0 deg unplated: 1(197.487,90.866)
  round 3.2 hole 3.2 unplated: ""(67.087,44.666) ""(67.087,130.166) ""(67.087,130.166) ""(154.587,44.366) ""(154.587,118.566) ""(159.937,104.266) ""(176.587,82.666) ""(176.587,117.166)

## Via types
v1: diameter 0.6, hole 0.3, Top Layer to Bottom Layer, 411 vias
v2: diameter 0.61, hole 0.305, Top Layer to Bottom Layer, 1 vias

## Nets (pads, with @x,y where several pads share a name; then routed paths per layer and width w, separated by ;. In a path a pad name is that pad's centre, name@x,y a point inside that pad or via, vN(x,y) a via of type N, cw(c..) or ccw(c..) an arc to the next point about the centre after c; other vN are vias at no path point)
1V8HUB: C12.2 U2.12 U2.28 | length 14.8
  Top Layer w0.3: U2.28@95.442,53.938 96.115,53.939 96.988,53.066 96.988,52.167 97.288,51.867 C12.2@97.287,51.666 97.587,51.966 97.587,54.666 99.287,56.366 v1(99.287,57.566) ; v1@99.787,60.466 100.245,60.924 U2.12@101.132,60.923
  Bottom Layer w0.3: v1(99.287,57.566) 99.287,59.966 v1@99.787,60.466
  other v1: 99.787,60.466
3V3HUB: C10.2 Q7.3 R2.2 R34.2 U2.13 U2.19 U2.21 U2.26 U14.8 | length 54.1
  Top Layer w0.145: v1@89.586,46.965 88.987,46.365 88.987,44.516 89.688,43.815 94.087,43.815 94.831,44.562 U14.8@95.286,44.562 ; 90.686,61.765 90.686,61.466 90.087,61.466 89.736,61.115 89.736,60.117 89.889,59.967 Q7.3@92.553,59.966 ; v1(90.687,51.766) R2.2@90.687,53.066
  Top Layer w0.15: R2.2@90.687,53.066 91.486,53.866 92.637,53.866 93.98,55.21 U2.26@95.442,55.208
  Top Layer w0.3: Q7.3@92.553,59.966 92.916,59.604 96.486,59.604 ; U2.26@95.442,55.208 96.13,55.209 96.587,55.666 ; U2.26@95.442,55.208 96.132,55.21 96.388,55.466 96.587,55.667 96.587,58.166 ; U2.21@95.443,58.334 96.987,58.266 97.287,58.611 97.287,59.221 96.9,59.604 U2.19@95.443,59.604 ; U2.19@95.442,59.653 96.874,59.655 97.186,59.964 v1@97.186,61.765 ; U2.13@101.132,61.558 100.195,61.559 v1(99.887,61.866) 99.887,62.366 100.287,62.766 102.586,62.766 103.587,63.767 C10.2@103.587,63.966
  Bottom Layer w0.145: v1@89.586,46.965 89.088,47.465 89.088,50.165 v1@90.686,51.765
  Bottom Layer w0.3: v1(97.187,61.766) 97.287,61.866 v1(99.887,61.866)
  other v1: 89.587,46.966
5V_1: 5V.1 R70.2 | length 1.3
  Top Layer w0.145: 5V.1@99.737,91.266 R70.2@101.087,91.266
+3V3: C15.1 C36.1 C41.2 C42.2 C43.2 C45.2 C46.2 C47.2 C48.2 C49.2 C50.2 C51.2 C52.1 C54.2 CN6.1 CN15.1 QWIIC.2 R29.2 R30.2 R37.2 R78.1 R79.1 RX485.2 RXCAN1.2 RXCAN.2 TX485.2 TXCAN1.2 TXCAN.2 U1.30 U7.5 U8.8 U11.1 U11.10 U11.11 U11.21 U11.31 U11.32 U11.33 U11.45 U11.50 U11.54 U11.75 U11.76 U11.99 U12.5 U13.1 U18.1 U18.14 | length 290.7
  Top Layer w0.145: R79.1@81.486,69.967 80.686,69.967 80.386,69.667 80.386,67.866 84.186,64.066 84.186,63.767 85.286,62.667 89.289,62.667 90.313,63.691 CN6.1@91.437,63.691 92.512,63.691 93.287,64.465 93.287,68.166 v1(93.387,68.166) ; R79.1@81.487,69.966 R78.1@82.987,69.966 ; C51.2@101.987,73.766 U11.21@103.787,73.766 ; C49.2@102.087,79.266 U11.10@103.787,79.266 ; C47.2@102.087,83.766 U11.1@103.787,83.766 104.987,83.766 105.887,84.666 U11.99@105.887,85.366 ; C49.2@102.587,78.766 U11.11@103.787,78.766 ; U11.21@103.787,73.766 104.986,73.767 107.887,70.866 U11.31@107.887,70.166 ; U11.99@105.887,85.366 C46.2@105.887,87.166 ; U11.31@107.887,70.166 107.887,69.366 C54.2@108.887,68.366 108.387,68.866 U11.32@108.387,70.166 v1(108.387,71.466) ; C54.2@108.887,68.366 U11.33@108.887,70.166 ; C50.2@114.987,68.366 114.887,68.466 U11.45@114.887,70.166 114.887,70.866 117.287,73.266 U11.54@118.987,73.266 C41.2@120.987,73.266 v1(120.287,73.966) ; 116.289,72.267 116.387,72.166 117.387,71.166 U11.50@117.387,70.166 117.387,68.966 ; C43.2@117.287,87.066 117.387,86.966 U11.76@117.387,85.366 117.387,84.666 118.287,83.766 U11.75@118.987,83.766 ; U11.75@118.987,83.766 125.537,83.766 ; 125.223,83.767 125.588,83.767 125.887,84.066 126.938,84.066 128.138,82.865 RXCAN1.2@128.137,81.466 ; U12.5@125.52,75.275 126.697,75.275 C45.2@126.787,75.366 ; C45.2@126.787,75.366 126.987,75.566 v1(126.987,76.266) ; CN15.1@127.087,56.996 128.417,56.996 C15.1@129.087,57.666 129.786,56.967 U18.1@130.439,56.967 130.587,56.967 130.587,58.816 U18.14@130.089,58.817 ; TXCAN1.2@128.137,79.966 RXCAN1.2@128.137,81.466 ; 130.587,58.258 130.595,58.266 v1(131.687,58.266) ; R29.2@135.539,57.517 R30.2@135.539,59.017 ; U7.5@165.828,104.398 165.828,104.325 166.037,104.116 166.887,104.116 C48.2@167.237,103.766 ; C48.2@167.237,103.766 168.588,102.415 168.588,101.483 169.253,100.818 ; 169.237,100.816 173.688,100.825 RXCAN.2@174.438,100.063 ; TXCAN.2@174.437,98.566 RXCAN.2@174.437,100.066 ; RX485.2@176.037,76.566 TX485.2@176.037,78.066
  Top Layer w0.2: U8.8@145.182,89.786 145.182,89.07 145.888,88.367 146.487,88.367 149.688,85.166 149.688,82.865 v1(153.187,79.366) 153.462,79.642 159.462,79.642 160.437,78.666 v1(160.587,78.666) 162.662,76.591 166.358,76.591 166.52,76.429 169.848,76.429 170.013,76.591 171.014,76.591 173.686,79.266 174.989,79.266 176.038,78.217 TX485.2@176.037,78.066
  Top Layer w0.3: v1(124.387,67.166) 127.336,67.165 129.838,69.667 139.088,69.667 139.787,70.366 146.388,70.366 147.237,71.214 v1(147.237,72.866) ; CN15.1@127.087,56.996 127.087,56.967 U18.1@130.439,56.967 ; U8.8@145.182,89.786 145.187,92.365 147.689,94.867 170.739,94.867 TXCAN.2@174.437,98.566
  Top Layer w0.5: 116.887,72.266 v1(118.987,70.166) ; QWIIC.2@123.787,48.816 v1(123.787,51.816) ; v1(124.387,63.566) 124.387,61.866 124.587,61.666
  Top Layer w0.8: C52.1@124.587,62.166 124.587,59.496 CN15.1@127.087,56.996
  Bottom Layer w0.145: v1(93.387,68.166) 93.387,69.765 93.688,70.066 93.793,70.165 103.066,70.165 103.368,69.865 ; 103.386,69.865 106.487,69.865 107.987,71.366 v1(108.387,71.466) ; v1(120.287,73.966) 121.087,73.965 121.788,73.266 123.988,73.266 v1(126.987,76.266)
  Bottom Layer w0.3: v1(131.687,58.266) v1(135.487,58.266) ; v1(147.237,72.866) 153.188,78.817 v1(153.187,79.366) ; 160.587,74.267 160.587,72.466 161.247,71.806 162.749,71.806 164.029,70.526 U1.30@164.366,70.526 ; 160.587,74.267 v1(160.587,78.666)
  Bottom Layer w0.5: v1(123.787,51.816) 123.787,53.696 CN15.1@127.087,56.996 ; v1(124.387,63.566) 124.087,63.866 124.087,66.866 v1(124.387,67.166)
  Bottom Layer w0.6: v1(118.987,70.166) 121.387,70.166 v1(124.387,67.166)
